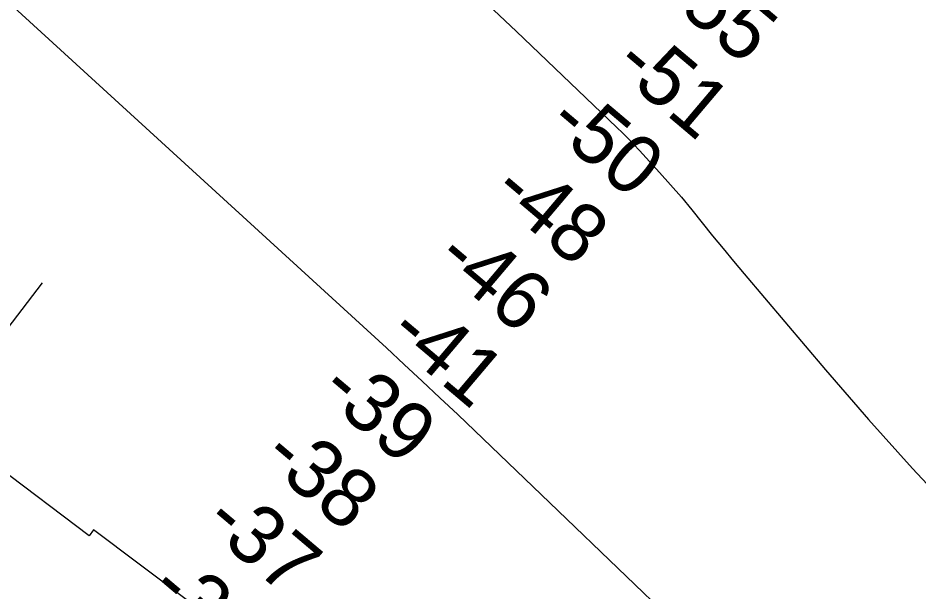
# Model space of a CAD drawing. Extents: x 3887375 to 3925618, y 296674 to 322633.
# Drawn here: x 3893221 to 3894247, y 311816 to 312470 of the extents above; entities that cross this region are included whole.
import ezdxf

# ---------------------------------------------------------------- set-up
doc = ezdxf.new("R2010")
doc.units = 0
for name, color, linetype in [('V-RIVR-EDGE', 7, 'Continuous'), ('V-RIVR-RANG', 7, 'Continuous'), ('V-RRAP-RVMT', 7, 'Continuous'), ('V-TOPO-DPTH', 7, 'Continuous'), ('V-TOPO-MAJR', 7, 'Continuous'), ('V-TOPO-MINR', 7, 'Continuous')]:
    doc.layers.add(name, color=color, linetype=linetype)

msp = doc.modelspace()

# ---------------------------------------------------------------- linework, layer by layer
at = {"layer": 'V-RIVR-EDGE'}
msp.add_spline([(3891468, 312834), (3891487, 312822.1), (3891534, 312792.8), (3891594.1, 312753.8), (3891650.4, 312718.7), (3891687.2, 312694.8), (3891715.8, 312678.7), (3891776, 312641.2), (3891829.3, 312607), (3891872.4, 312576.3), (3891897.6, 312554.9), (3891920.4, 312540.3), (3891948.5, 312515.9), (3892002.8, 312474.5), (3892042.1, 312440.4), (3892073.6, 312415.6), (3892102.2, 312395.6), (3892133.2, 312371.2), (3892200.1, 312321.5), (3892242.8, 312292.8), (3892291.7, 312258.2), (3892341.7, 312219.2), (3892369.3, 312198.3), (3892390.1, 312181.2), (3892413.9, 312163.2), (3892453.6, 312136.4), (3892487.1, 312113.5), (3892522, 312087.6), (3892555, 312065.2), (3892591.3, 312042.3), (3892628.2, 312016), (3892662.1, 311994.1), (3892686.8, 311979.9), (3892764.9, 311931.2), (3892805.1, 311902.9), (3892836.2, 311880.5), (3892877.9, 311852.7), (3892924.4, 311821.5), (3892965.1, 311793.2), (3893024.8, 311754.2), (3893079.1, 311715.7), (3893108.1, 311694.3), (3893146.4, 311668.9), (3893184.7, 311638.7), (3893227.9, 311606.1), (3893285.1, 311562.7), (3893338.9, 311523.7), (3893381.5, 311493), (3893441.7, 311449.7), (3893482.4, 311420), (3893505.6, 311395.6), (3893524.5, 311379.1), (3893555.1, 311358.1), (3893588.5, 311330.3), (3893620.5, 311305.5), (3893676.2, 311256.3), (3893730, 311212.5), (3893771.7, 311175), (3893804.2, 311145.3), (3893965, 311005.5), (3893991.7, 310979.2), (3894015.4, 310950.5), (3894041.1, 310924.2), (3894068.7, 310897.9)], degree=3, dxfattribs=at)
at = {"layer": 'V-RIVR-RANG'}
msp.add_line((3892910.1, 311722.5), (3893249.2, 312168.1), dxfattribs=at)
at = {"layer": 'V-RRAP-RVMT'}
for p, q in [((3893302.3, 311879.5), (3893196.9, 311959)), ((3893307.4, 311886.3), (3893302.3, 311879.5)), ((3893412.8, 311806.7), (3893307.4, 311886.3))]:
    msp.add_line(p, q, dxfattribs=at)
at = {"layer": 'V-TOPO-DPTH'}
msp.add_lwpolyline([(3894258.7, 311498), (3894243.2, 311513.3), (3894227.6, 311528.7), (3894212, 311544), (3894108.3, 311645.4), (3894040.7, 311711.3), (3893973, 311777.1), (3893905.1, 311842.6), (3893837, 311908), (3893722.4, 312017.8), (3893702.2, 312036.9), (3893682, 312056), (3893661.6, 312074.9), (3893641.2, 312093.7), (3893136.8, 312555.4), (3892611.1, 313003.7), (3892589.6, 313022), (3892568, 313040.2), (3892546.4, 313058.4), (3892524.7, 313076.4), (3892192.7, 313352.4)], dxfattribs=at)
msp.add_lwpolyline([(3894258.7, 311498), (3894243.2, 311513.3), (3894227.6, 311528.7), (3894212, 311544), (3894108.3, 311645.4), (3894040.7, 311711.3), (3893973, 311777.1), (3893905.1, 311842.6), (3893837, 311908), (3893722.4, 312017.8), (3893702.2, 312036.9), (3893682, 312056), (3893661.6, 312074.9), (3893641.2, 312093.7), (3893136.8, 312555.4), (3892611.1, 313003.7), (3892589.6, 313022), (3892568, 313040.2), (3892546.4, 313058.4), (3892524.7, 313076.4), (3892192.7, 313352.4)], dxfattribs=at)
at = {"layer": 'V-TOPO-MAJR'}
msp.add_lwpolyline([(3893724.8, 312515.8), (3893789.2, 312455.1), (3893903.9, 312345.3), (3893910.4, 312338.9), (3893916.9, 312332.4), (3893923.2, 312325.8), (3893929.5, 312319.1), (3893952.5, 312293.8), (3893965.1, 312279.8), (3893977.4, 312265.6), (3893989.4, 312251.1), (3894001.2, 312236.4), (3894012.9, 312221.7), (3894024.8, 312207.1), (3894036.7, 312192.6), (3894048.8, 312178.1), (3894141.5, 312068.7), (3894190.6, 312012.1), (3894240.6, 311956.3), (3894291.8, 311901.7)], dxfattribs=at)
at = {"layer": 'V-TOPO-MINR'}
msp.add_lwpolyline([(3892192.7, 313352.4), (3892524.7, 313076.4), (3892546.4, 313058.4), (3892568, 313040.2), (3892589.6, 313022), (3892611.1, 313003.7), (3893136.8, 312555.4), (3893641.2, 312093.7), (3893661.6, 312074.9), (3893682, 312056), (3893702.2, 312036.9), (3893722.4, 312017.8), (3893837, 311908), (3893905.1, 311842.6), (3893973, 311777.1), (3894040.7, 311711.3), (3894108.3, 311645.4), (3894212, 311544), (3894227.6, 311528.7), (3894243.2, 311513.3), (3894258.7, 311498)], dxfattribs=at)

# ---------------------------------------------------------------- texts
at = {"layer": 'V-RIVR-RANG'}
for s, p in [('-55', (3893950.5, 312498.4)), ('-51', (3893897.6, 312412.2)), ('-50', (3893821.6, 312345.5)), ('-48', (3893758.6, 312267.8)), ('-46', (3893694.3, 312191.3)), ('-41', (3893640.2, 312106)), ('-39', (3893562.1, 312041.1)), ('-38', (3893496.8, 311965.4)), ('-37', (3893430.4, 311890.6)), ('-36', (3893367.7, 311812.7))]:
    msp.add_text(s, height=67, rotation=319.7813, dxfattribs=at).set_placement(p)

doc.saveas('drawing.dxf')
